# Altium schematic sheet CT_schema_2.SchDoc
size 276 x 169 mm
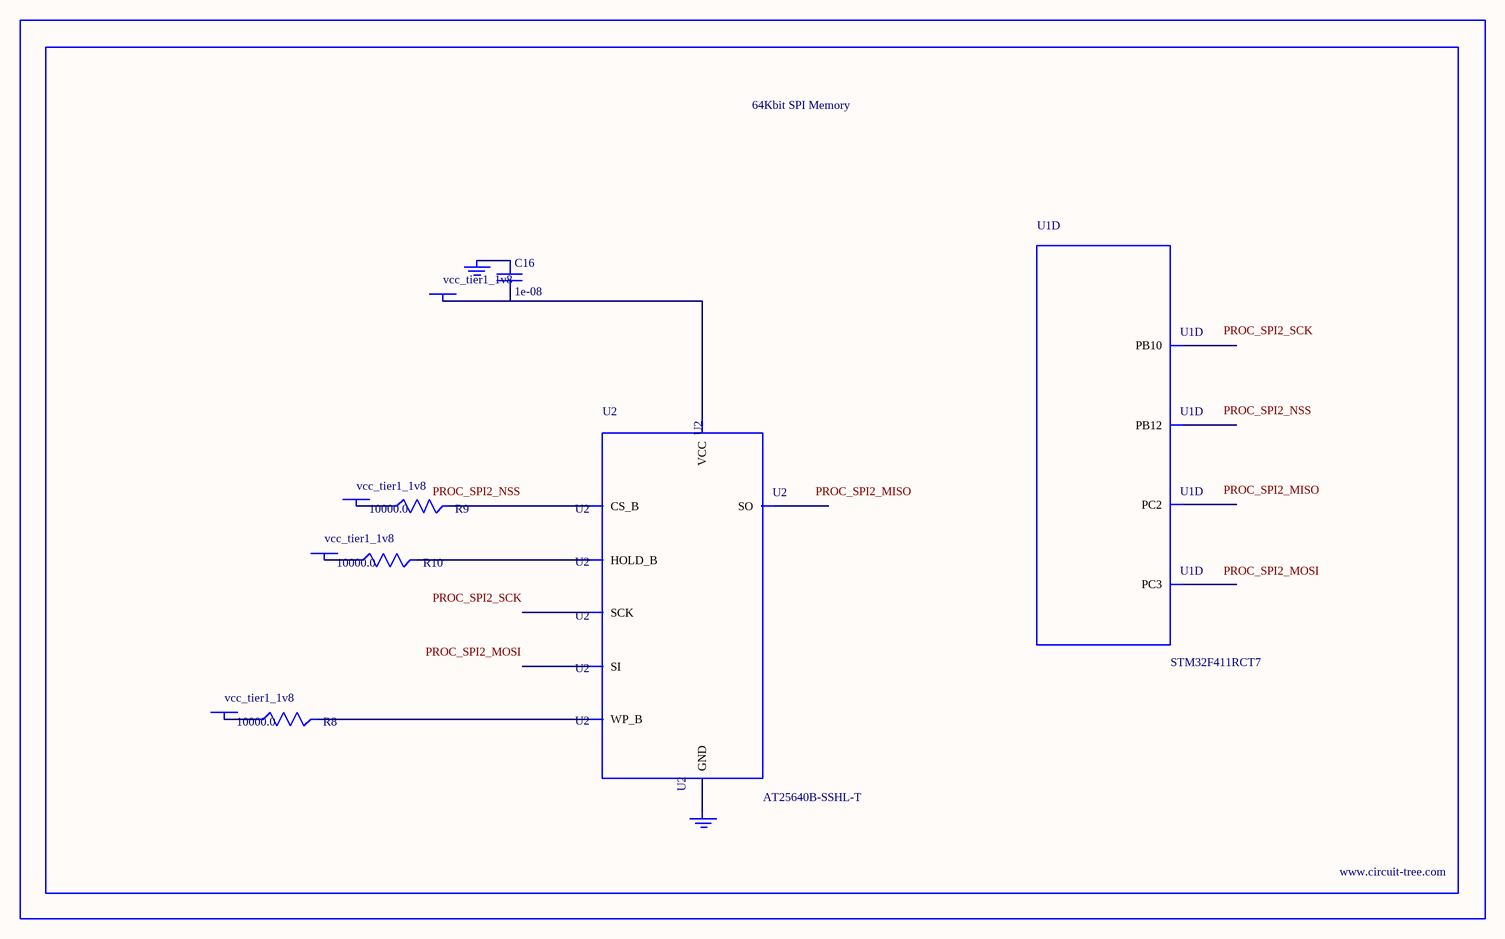
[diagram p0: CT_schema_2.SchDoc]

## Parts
BORDER1  (no value)
C16  1e-08  [C0402]
GND_INSTANCE_1_0  (no value)
GND_INSTANCE_1_1  (no value)
POWER_INSTANCE_1_0  vcc_tier1_1v8
POWER_INSTANCE_1_1  vcc_tier1_1v8
POWER_INSTANCE_1_2  vcc_tier1_1v8
POWER_INSTANCE_1_3  vcc_tier1_1v8
R8  10000.0  [R0603]
R9  10000.0  [R0603]
R10  10000.0  [R0603]
U1  STM32F411RCT7  [LQFP64]  (part D of 8)
U2  AT25640B-SSHL-T  [SOIC-8]

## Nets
NetC16_1: C16.1 GND_INSTANCE_1_0.0(GND)
NetC16_2: C16.2 POWER_INSTANCE_1_3.0(PWR) U2.8(VCC)
NetGND_INSTANCE_1_1_0: GND_INSTANCE_1_1.0(GND) U2.4(GND)
NetPOWER_INSTANCE_1_0_0: POWER_INSTANCE_1_0.0(PWR) R9.1
NetPOWER_INSTANCE_1_1_0: POWER_INSTANCE_1_1.0(PWR) R8.1
NetPOWER_INSTANCE_1_2_0: POWER_INSTANCE_1_2.0(PWR) R10.1
NetR8_2: R8.2 U2.3(WP_B)
NetR9_2: R9.2 U2.1(CS_B)
NetR10_2: R10.2 U2.7(HOLD_B)

Not connected (* = marked no-connect by the designer): U1 10(PC2) 11(PC3) 29(PB10) 33(PB12); U2 2(SO) 5(SI) 6(SCK)

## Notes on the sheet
- Labels drawn without touching a wire or pin: PROC_SPI2_MISO, PROC_SPI2_MOSI, PROC_SPI2_NSS, PROC_SPI2_SCK

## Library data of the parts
BORDER1 = BORDER_PAGE1
C16 = C0402C103K3RAC
GND_INSTANCE_1_0 GND_INSTANCE_1_1 = GND
POWER_INSTANCE_1_0-POWER_INSTANCE_1_3 = PWR
R8-R10 = RC0603JR-0710KL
